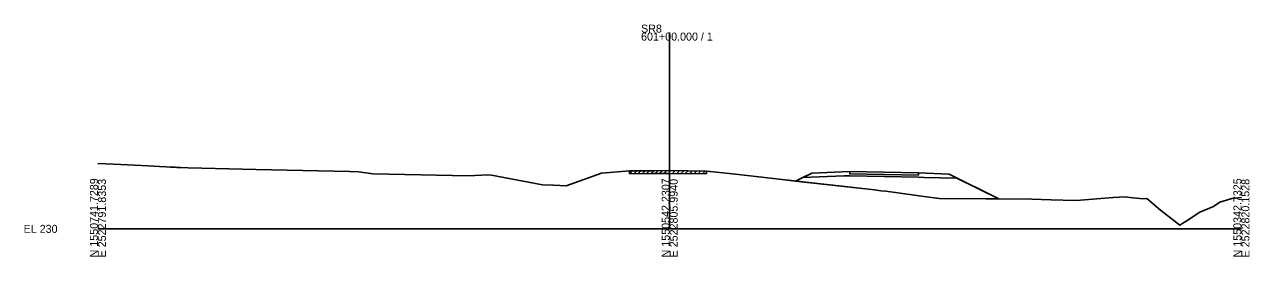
# Model space of a CAD drawing. Extents: x -26 to 2803, y -10 to 19537.
# Drawn here: x -25.7 to 402.8, y 9490.3 to 9571.5 of the extents above; entities that cross this region are included whole.
import ezdxf

# ---------------------------------------------------------------- set-up
doc = ezdxf.new("R2010")
doc.units = 0
for name, color, linetype in [('50', 7, 'Continuous'), ('XS_CELL', 7, 'Continuous'), ('XS_M_MULTI', 7, 'Continuous'), ('XS_M_SHAPES_EARTHWORK', 7, 'Continuous'), ('XS_P_FINISHED_GRADE', 7, 'Continuous'), ('XS_P_SUBGRADE_GRANULAR', 7, 'Continuous'), ('XS_P_SUBGRADE_PAVEMENT', 7, 'Continuous'), ('XS_X_GROUND', 7, 'Continuous')]:
    doc.layers.add(name, color=color, linetype=linetype)

msp = doc.modelspace()

# ---------------------------------------------------------------- linework, layer by layer
at = {"layer": '50'}
for p, q in [((185.95, 9519.3), (186.96, 9520.31)), ((185.95, 9519.3), (185.95, 9520.3)), ((185.95, 9519.3), (193.89, 9519.36)), ((187.45, 9519.31), (188.46, 9520.32)), ((188.95, 9519.32), (189.96, 9520.33)), ((190.45, 9519.33), (191.46, 9520.34)), ((191.95, 9519.34), (192.96, 9520.35)), ((193.45, 9519.35), (194.46, 9520.36)), ((193.89, 9519.36), (199.58, 9519.4)), ((194.95, 9519.36), (195.96, 9520.37)), ((196.45, 9519.38), (197.46, 9520.38)), ((197.96, 9519.39), (198.96, 9520.39)), ((199.46, 9519.4), (200.45, 9520.39)), ((199.58, 9519.4), (200, 9519.39)), ((200, 9519.39), (212.93, 9519.23)), ((200.96, 9519.38), (201.94, 9520.37)), ((202.46, 9519.36), (203.44, 9520.35)), ((203.96, 9519.34), (204.95, 9520.33)), ((205.46, 9519.32), (206.45, 9520.31)), ((206.96, 9519.3), (207.95, 9520.29)), ((208.46, 9519.29), (209.45, 9520.27)), ((209.96, 9519.27), (210.95, 9520.25)), ((211.46, 9519.25), (212.45, 9520.23)), ((212.93, 9520.23), (212.93, 9519.23))]:
    msp.add_line(p, q, dxfattribs=at)
at = {"layer": 'XS_CELL'}
for p, q in [((200, 9500), (200, 9568.7)), ((0, 9500), (200, 9500)), ((200, 9500), (400, 9500))]:
    msp.add_line(p, q, dxfattribs=at)
at = {"layer": 'XS_M_MULTI'}
for p, q in [((243.99, 9516.74), (249.71, 9519.51)), ((249.71, 9519.51), (263, 9520.04)), ((263, 9520.04), (275, 9519.8)), ((275, 9519.8), (287, 9519.56)), ((287, 9519.56), (297.79, 9519.13)), ((297.79, 9519.13), (315.16, 9510.47))]:
    msp.add_line(p, q, dxfattribs=at)
for points in [[(0, 9522.9), (8.01, 9522.5), (17.52, 9522.02), (21.59, 9521.81), (23.84, 9521.7), (25.27, 9521.63), (26.27, 9521.58), (26.99, 9521.54), (27.55, 9521.51), (27.99, 9521.49), (28.88, 9521.44), (31.57, 9521.34), (55.27, 9520.79), (88.07, 9520.07), (91.19, 9519.95), (96.22, 9519.27), (129.63, 9518.5), (136.37, 9518.91), (137.64, 9518.73), (155.48, 9515.46), (159.4, 9515.27), (163.74, 9515.07), (176.18, 9519.47), (185.95, 9520.3), (193.89, 9520.36), (199.58, 9520.4), (200, 9520.39), (212.93, 9520.23), (221.98, 9519.24), (223.01, 9519.13), (239.3, 9517.27), (243.99, 9516.74)], [(315.16, 9510.47), (326.73, 9510.37), (333.47, 9510.17), (341.75, 9509.92), (343.69, 9510.09), (355.19, 9511.01), (359.3, 9511.22), (360.98, 9510.97), (365.68, 9510.46), (366.91, 9510.61), (371.71, 9506.48), (378.51, 9501.26), (379.48, 9502.03), (380.31, 9502.44), (385.41, 9505.8), (390.22, 9507.86), (392.42, 9509.29), (396.3, 9510.51), (396.69, 9510.67), (400, 9510.96)]]:
    msp.add_lwpolyline(points, dxfattribs=at)
at = {"layer": 'XS_M_SHAPES_EARTHWORK'}
for points in [[(263, 9518.54), (275, 9518.3), (287, 9518.06), (289, 9518.02), (300.48, 9517.79), (315.16, 9510.47), (294.41, 9510.67), (290.71, 9511.13), (275.66, 9513.15), (273.85, 9513.31), (271.66, 9513.6), (243.99, 9516.74), (246.6, 9518.01), (261, 9518.58)], [(263, 9518.54), (275, 9518.3), (287, 9518.06), (289, 9518.02), (300.48, 9517.79), (297.79, 9519.13), (287, 9519.56), (287, 9518.81), (275, 9519.05), (263, 9519.29), (263, 9520.04), (249.71, 9519.51), (246.6, 9518.01), (261, 9518.58)], [(275, 9519.8), (287, 9519.56), (287, 9518.81), (275, 9519.05), (263, 9519.29), (263, 9520.04)]]:
    msp.add_lwpolyline(points, close=True, dxfattribs=at)
at = {"layer": 'XS_P_FINISHED_GRADE'}
for p, q in [((249.71, 9519.51), (243.99, 9516.74)), ((263, 9520.04), (249.71, 9519.51)), ((263, 9520.04), (275, 9519.8)), ((275, 9519.8), (287, 9519.56)), ((287, 9519.56), (297.79, 9519.13)), ((297.79, 9519.13), (315.16, 9510.47))]:
    msp.add_line(p, q, dxfattribs=at)
at = {"layer": 'XS_P_SUBGRADE_GRANULAR'}
for p, q in [((261, 9518.58), (246.6, 9518.01)), ((263, 9518.54), (261, 9518.58)), ((263, 9518.54), (275, 9518.3)), ((275, 9518.3), (287, 9518.06)), ((287, 9518.06), (289, 9518.02)), ((289, 9518.02), (300.48, 9517.79))]:
    msp.add_line(p, q, dxfattribs=at)
at = {"layer": 'XS_P_SUBGRADE_PAVEMENT'}
for p, q in [((263, 9519.29), (263, 9520.04)), ((263, 9519.29), (275, 9519.05)), ((275, 9519.05), (287, 9518.81)), ((287, 9518.81), (287, 9519.56))]:
    msp.add_line(p, q, dxfattribs=at)
at = {"layer": 'XS_X_GROUND'}
msp.add_lwpolyline([(0, 9522.9), (8.01, 9522.5), (17.52, 9522.02), (21.59, 9521.81), (23.84, 9521.7), (25.27, 9521.63), (26.27, 9521.58), (26.99, 9521.54), (27.55, 9521.51), (27.99, 9521.49), (28.88, 9521.44), (31.57, 9521.34), (55.27, 9520.79), (88.07, 9520.07), (91.19, 9519.95), (96.22, 9519.27), (129.63, 9518.5), (136.37, 9518.91), (137.64, 9518.73), (155.48, 9515.46), (159.4, 9515.27), (163.74, 9515.07), (176.18, 9519.47), (185.95, 9520.3), (193.89, 9520.36), (199.58, 9520.4), (200, 9520.39), (212.93, 9520.23), (221.98, 9519.24), (223.01, 9519.13), (239.3, 9517.27), (271.66, 9513.6), (273.85, 9513.31), (275.66, 9513.15), (290.71, 9511.13), (294.41, 9510.67), (326.73, 9510.37), (333.47, 9510.17), (341.75, 9509.92), (343.69, 9510.09), (355.19, 9511.01), (359.3, 9511.22), (360.98, 9510.97), (365.68, 9510.46), (366.91, 9510.61), (371.71, 9506.48), (378.51, 9501.26), (379.48, 9502.03), (380.31, 9502.44), (385.41, 9505.8), (390.22, 9507.86), (392.42, 9509.29), (396.3, 9510.51), (396.69, 9510.67), (400, 9510.96)], dxfattribs=at)

# ---------------------------------------------------------------- texts
at = {"layer": 'XS_CELL'}
for s, p in [('SR8', (190, 9568.7)), ('601+00.000 / 1', (190, 9565.9)), ('EL 230', (-26, 9498.6))]:
    msp.add_text(s, height=2.8, dxfattribs=at).set_placement(p)
for s, p in [('N 1550741.7289', (0, 9490)), ('E 2522791.8353', (2.8, 9490)), ('N 1550542.2307', (200, 9490)), ('E 2522805.9940', (202.8, 9490)), ('N 1550342.7325', (400, 9490)), ('E 2522820.1528', (402.8, 9490))]:
    msp.add_text(s, height=2.8, rotation=90, dxfattribs=at).set_placement(p)

doc.saveas('drawing.dxf')
